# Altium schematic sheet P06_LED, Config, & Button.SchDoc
size 386 x 246 mm
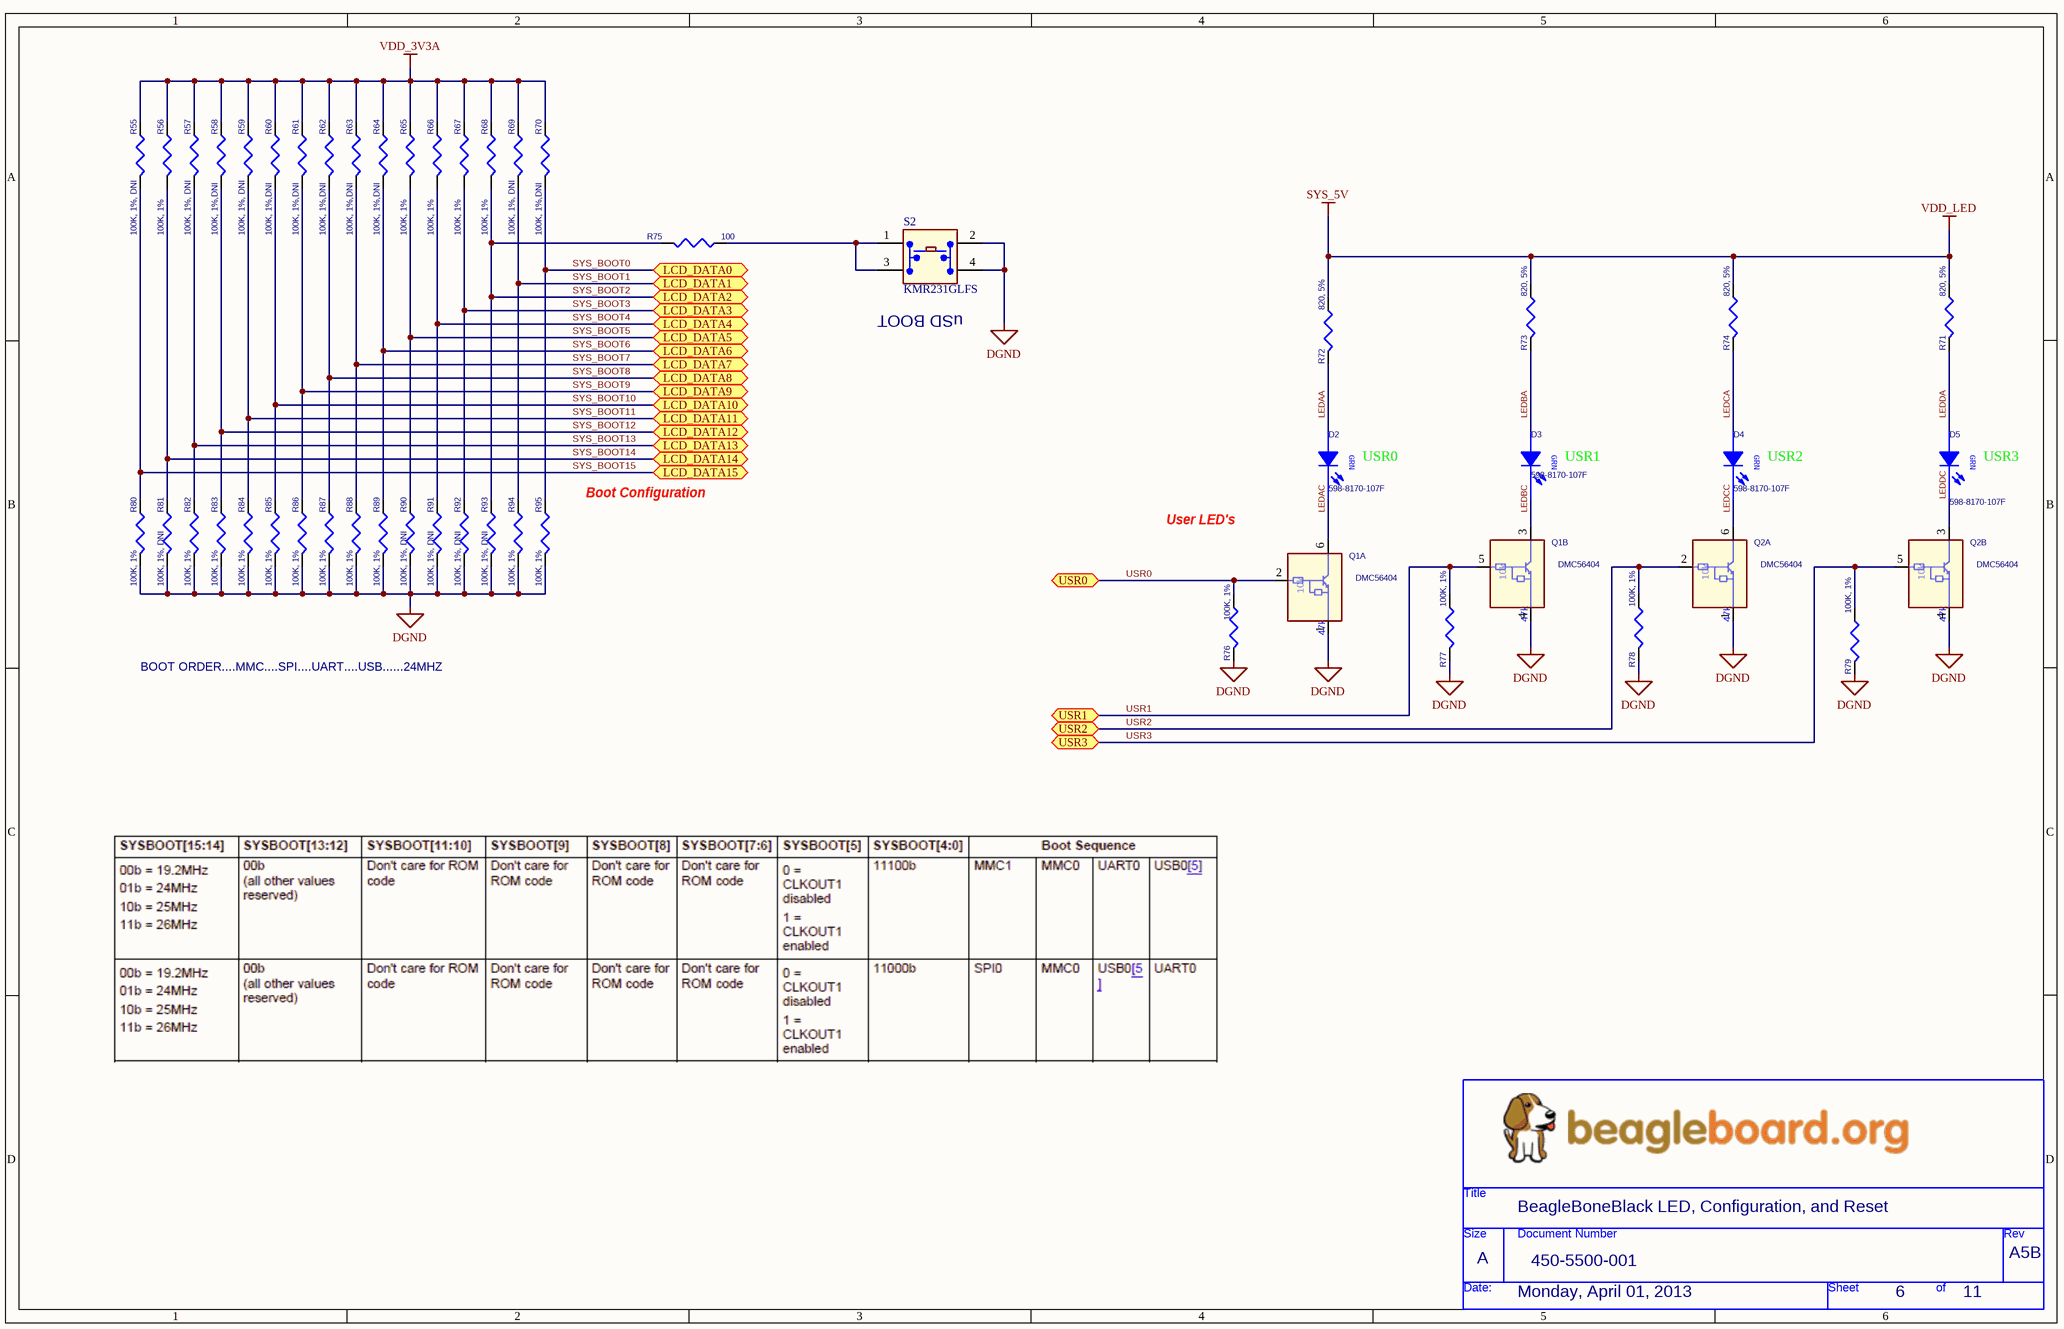
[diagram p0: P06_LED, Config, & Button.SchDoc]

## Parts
*  Page Create Date: Monday, April 01, 2013  Doc: 450-5500-001  RevCode: A5B  Title: BeagleBoneBlack LED, Configuration, and Reset  Page Size: A  Page Number: 6  Page Count: 11  (hidden comment: BeagleBoard_org)  (graphical)
D2  598-8170-107F  [LED_0603]
D3  598-8170-107F  [LED_0603]
D4  598-8170-107F  [LED_0603]
D5  598-8170-107F  [LED_0603]
Q1  DMC56404  [SMini6-F3-B]  (parts A,B of 2)
Q2  DMC56404  [SMini6-F3-B]  (parts A,B of 2)
R55  100K, 1%, DNI  [402]
R56  100K, 1%  [402]
R57  100K, 1%, DNI  [402]
R58  100K, 1%,DNI  [402]
R59  100K, 1%, DNI  [402]
R60  100K, 1%,DNI  [402]
R61  100K, 1%,DNI  [402]
R62  100K, 1%,DNI  [402]
R63  100K, 1%,DNI  [402]
R64  100K, 1%,DNI  [402]
R65  100K, 1%  [402]
R66  100K, 1%  [402]
R67  100K, 1%  [402]
R68  100K, 1%  [402]
R69  100K, 1%, DNI  [402]
R70  100K, 1%,DNI  [402]
R71  820, 5%  [402]
R72  820, 5%  [402]
R73  820, 5%  [402]
R74  820, 5%  [402]
R75  100  [402]
R76  100K, 1%  [402]
R77  100K, 1%  [402]
R78  100K, 1%  [402]
R79  100K, 1%  [402]
R80  100K, 1%  [402]
R81  100K, 1%, DNI  [402]
R82  100K, 1%  [402]
R83  100K, 1%  [402]
R84  100K, 1%  [402]
R85  100K, 1%  [402]
R86  100K, 1%  [402]
R87  100K, 1%  [402]
R88  100K, 1%  [402]
R89  100K, 1%  [402]
R90  100K, 1%, DNI  [402]
R91  100K, 1%, DNI  [402]
R92  100K, 1%, DNI  [402]
R93  100K, 1%, DNI  [402]
R94  100K, 1%  [402]
R95  100K, 1%  [402]
S2  KMR231GLFS  [SW4SMD_63X161LS]

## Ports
LCD_DATA0, LCD_DATA1, LCD_DATA2, LCD_DATA3, LCD_DATA4, LCD_DATA5, LCD_DATA6, LCD_DATA7, LCD_DATA8, LCD_DATA9, LCD_DATA10, LCD_DATA11, LCD_DATA12, LCD_DATA13, LCD_DATA14, LCD_DATA15, USR0, USR1, USR2, USR3

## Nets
DGND: Q1.1 Q1.4 Q2.1 Q2.4 R76.2 R77.2 R78.2 R79.2 R80.2 R81.2 R82.2 R83.2 R84.2 R85.2 R86.2 R87.2 R88.2 R89.2 R90.2 R91.2 R92.2 R93.2 R94.2 R95.2 S2.2(A2) S2.4
SYS_5V: R71.1 R72.1 R73.1 R74.1  [also labelled VDD_LED]
VDD_3V3A: R55.1 R56.1 R57.1 R58.1 R59.1 R60.1 R61.1 R62.1 R63.1 R64.1 R65.1 R66.1 R67.1 R68.1 R69.1 R70.1
LEDAA: D2.2(A) R72.2
LEDAC: D2.1(C) Q1.6
LEDBA: D3.2(A) R73.2
LEDBC: D3.1(C) Q1.3
LEDCA: D4.2(A) R74.2
LEDCC: D4.1(C) Q2.6
LEDDA: D5.2(A) R71.2
LEDDC: D5.1(C) Q2.3
SYS_BOOT0: R70.2 R95.1 ; port LCD_DATA0
SYS_BOOT1: R69.2 R94.1 ; port LCD_DATA1
SYS_BOOT2: R68.2 R75.1(P1) R93.1 ; port LCD_DATA2
SYS_BOOT3: R67.2 R92.1 ; port LCD_DATA3
SYS_BOOT4: R66.2 R91.1 ; port LCD_DATA4
SYS_BOOT5: R65.2 R90.1 ; port LCD_DATA5
SYS_BOOT6: R64.2 R89.1 ; port LCD_DATA6
SYS_BOOT7: R63.2 R88.1 ; port LCD_DATA7
SYS_BOOT8: R62.2 R87.1 ; port LCD_DATA8
SYS_BOOT9: R61.2 R86.1 ; port LCD_DATA9
SYS_BOOT10: R60.2 R85.1 ; port LCD_DATA10
SYS_BOOT11: R59.2 R84.1 ; port LCD_DATA11
SYS_BOOT12: R58.2 R83.1 ; port LCD_DATA12
SYS_BOOT13: R57.2 R82.1 ; port LCD_DATA13
SYS_BOOT14: R56.2 R81.1 ; port LCD_DATA14
SYS_BOOT15: R55.2 R80.1 ; port LCD_DATA15
USR0: Q1.2 R76.1 ; port USR0
USR1: Q1.5 R77.1 ; port USR1
USR2: Q2.2 R78.1 ; port USR2
USR3: Q2.5 R79.1 ; port USR3
NetR75_2: R75.2(P2) S2.1(A1) S2.3(A3)

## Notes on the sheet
- (near S2) uSD BOOT
- (near D2) USR0
- (near D3) USR1
- (near D4) USR2
- (near D5) USR3
- (near R95) Boot Configuration
- User LED's
- BOOT ORDER....MMC....SPI....UART....USB......24MHZ

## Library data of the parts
D2-D5 = LED_LTST-C150GKT: LED GREEN CLEAR 0805 SMD; Manufacturer: Lite-On Inc; Manufacturer Part Number: LTST-C170KGKT; CLASS: DISCRETE; TN: 257-0020-000; Current - Test: 20mA; Lens Style/Size: Rectangle with Flat Top, 1.4mm x 1.25mm; Millicandela Rating: 35mcd; Viewing Angle: 130°; Voltage - Forward (Vf) Typ: 2V; Wavelength - Dominant: 571nm; Wavelength - Peak: 574nm
Q1 Q2 = RN1907: TRANS PREBIASED DUAL NPN SOT363; Manufacturer: Toshiba; Manufacturer Part Number: DDC114YU-7-F; Order# 2: BCR135S; ATLStockNo1: 2130.0137; ATLStockNo2: 2130.01; Transistor Type: 2 NPN - Pre-Biased (Dual); Current - Collector (Ic) (Max): 100mA; Voltage - Collector Emitter Breakdown (Max): 50V; Resistor - Base (R1) (Ohms): 10k; Resistor - Emitter Base (R2) (Ohms): 47k; DC Current Gain (hFE) (Min) @ Ic, Vce: 68 @ 10mA, 5V; Vce Saturation (Max) @ Ib, Ic: 300mV @ 250µA, 5mA; Current - Collector Cutoff (Max): 500nA; Frequency - Transition: 250MHz; Power - Max: 200mW
R55-R70 R76-R95 = RES_100K_1/16W_1%_0402: RES 100K OHM 1/16W 1% 0402 SMD; Manufacturer: Stackpole Electronics Inc; Manufacturer Part Number: RMCF0402FT100K; Power (Watts): 0.063W, 1/16W; Temperature Coefficient: ±100ppm/°C
R71-R74 = RES_470_1/10W_5%_0402: RES 820 OHM 1/10W 5% 0402 SMD; Manufacturer: Yageo; Manufacturer Part Number: RC0402JR-07820RL; Power (Watts): 0.063W, 1/16W; Resistance (Ohms): 820; Temperature Coefficient: ±100ppm/°C
R75 = RES SMD: RES 100 OHM 1/10W 5% 0402 SMD; Manufacturer: Panasonic Electronic Components; Manufacturer Part Number: ERJ-2RKF1000X; Power (Watts): 0.1W, 1/10W; Temperature Coefficient: ±100ppm/°C
S2 = KMR2: Microminiature Tact Switch for SMT; Manufacturer: C&K Components; Circuit: SPST-NO; Switch Function: Off-Mom; Contact Rating @ Voltage: 0.05A @ 32VDC; Actuator Type: Standard; Actuator Height off PCB, from Pins: 1.90mm; Actuator Orientation: Top Actuated; Outline: 4.60mm x 2.80mm; Illumination: Non-Illuminated; Operating Force: 300gf; Switch Travel: 0.25mm; Mechanical Life: 150,000 Cycles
